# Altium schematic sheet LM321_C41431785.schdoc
size 127 x 101 mm
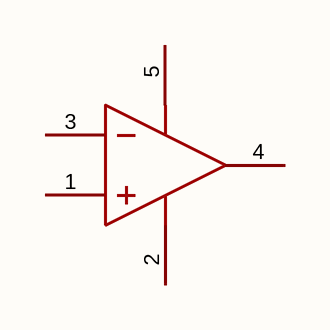
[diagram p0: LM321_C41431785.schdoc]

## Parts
U?  lm321_c41431785  [SOT-23-5_L3.0-W1.7-P0.95-LS2.8-BR]  (value not drawn)

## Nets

Not connected (* = marked no-connect by the designer): U? 1(IN+) 2(VSS) 3(IN-) 4(OUT) 5(VDD)

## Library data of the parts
U? = lm321_c41431785: 放大器数:1;轨到轨:-;增益带宽积(GBW):1MHz;输入失调电压(Vos):5mV;压摆率(SR):400V/ms;输入偏置电流(Ib):150nA;; Manufacturer: TECH PUBLIC(台舟); ManufacturerPart: LM321; AddInBom: yes; ModelId: 0a2a1b8f50944f73965918ad6e5fe167; ModelName: SOT-23-5_L2.9-W1.6-H1.1-LS2.8-P0.95; ModelTransform: 114.173,109.636,0,180,0,0,0,0,0; Number of Channels: 1; Maximum Power Supply Range (Vdd-Vss): 32V; Gain Bandwidth Product: 1MHz; Vos - Input Offset Voltage: 5mV; Ib - Input Bias Current: 150nA; Input Offset Current(Ios): 3nA; Common Mode Rejection Ratio(CMRR): 100dB; Quiescent Current: 100uA; Single supply: 3V~32V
